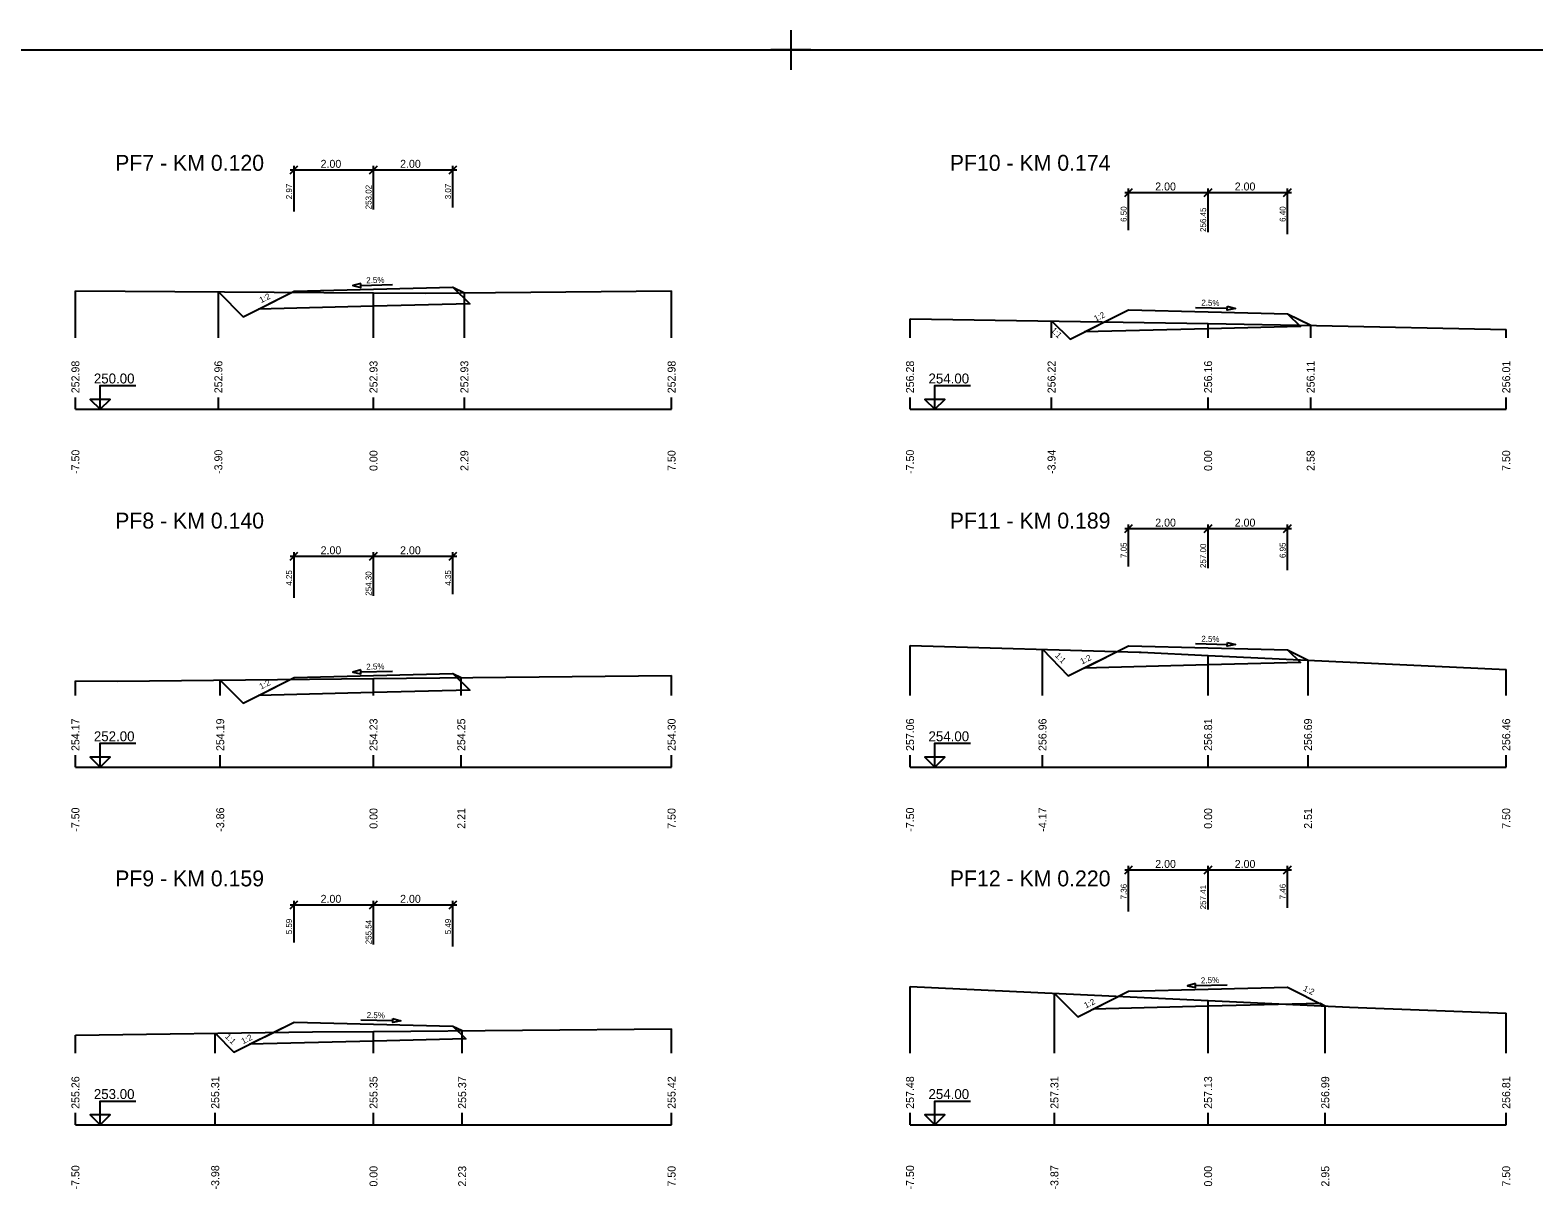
# Model space of a CAD drawing. Extents: x -5 to 1895, y -2 to 602.
# Drawn here: x 438.6 to 817, y 308.1 to 602.4 of the extents above; entities that cross this region are included whole.
import ezdxf

# ---------------------------------------------------------------- set-up
doc = ezdxf.new("R2010")
doc.units = 0
for name, color, linetype in [('KOTA', 7, 'Continuous'), ('KOTA_DELKY', 7, 'Continuous'), ('KOTA_DELKY_CONT', 7, 'Continuous'), ('NS_TELESO_VOZOVKY', 7, 'Continuous'), ('NS_V_PF', 7, 'Continuous'), ('REZY_PF_PUVODNI', 7, 'Continuous'), ('SESTAVY_REZU_PF', 7, 'Continuous'), ('SKLON', 7, 'Continuous'), ('SVK', 7, 'Continuous')]:
    doc.layers.add(name, color=color, linetype=linetype)

msp = doc.modelspace()

# ---------------------------------------------------------------- linework, layer by layer
for p, q in [((630, 602.39), (630, 592.39)), ((630, 602.39), (630, 592.39)), ((630, 602.39), (630, 592.39)), ((630, 602.39), (630, 592.39)), ((630, 602.39), (630, 592.39)), ((630, 602.39), (630, 592.39)), ((630, 602.39), (630, 592.39)), ((630, 602.39), (630, 592.39)), ((630, 602.39), (630, 592.39)), ((630, 602.39), (630, 592.39)), ((630, 602.39), (630, 592.39)), ((630, 602.39), (630, 592.39)), ((630, 602.39), (630, 592.39)), ((630, 602.39), (630, 592.39)), ((630, 602.39), (630, 592.39)), ((630, 602.39), (630, 592.39)), ((630, 602.39), (630, 592.39)), ((630, 602.39), (630, 592.39)), ((635, 597.39), (625, 597.39)), ((635, 597.39), (625, 597.39)), ((635, 597.39), (625, 597.39)), ((635, 597.39), (625, 597.39)), ((635, 597.39), (625, 597.39)), ((635, 597.39), (625, 597.39)), ((635, 597.39), (625, 597.39)), ((635, 597.39), (625, 597.39)), ((635, 597.39), (625, 597.39)), ((635, 597.39), (625, 597.39)), ((635, 597.39), (625, 597.39)), ((635, 597.39), (625, 597.39)), ((635, 597.39), (625, 597.39)), ((635, 597.39), (625, 597.39)), ((635, 597.39), (625, 597.39)), ((635, 597.39), (625, 597.39)), ((635, 597.39), (625, 597.39)), ((635, 597.39), (625, 597.39))]:
    msp.add_line(p, q)
msp.add_lwpolyline([(0, 597.39), (1890, 597.39), (1890, 3.39), (0, 3.39)], close=True)
at = {"layer": 'KOTA'}
for points in [[(456.22, 509.5), (453.72, 509.5), (456.22, 507), (456.22, 513), (465.22, 513)], [(666.22, 509.5), (663.72, 509.5), (666.22, 507), (666.22, 513), (675.22, 513)], [(456.22, 507), (458.72, 509.5), (456.22, 509.5)], [(666.22, 507), (668.72, 509.5), (666.22, 509.5)], [(456.22, 419.5), (453.72, 419.5), (456.22, 417), (456.22, 423), (465.22, 423)], [(666.22, 419.5), (663.72, 419.5), (666.22, 417), (666.22, 423), (675.22, 423)], [(456.22, 417), (458.72, 419.5), (456.22, 419.5)], [(666.22, 417), (668.72, 419.5), (666.22, 419.5)], [(456.22, 329.5), (453.72, 329.5), (456.22, 327), (456.22, 333), (465.22, 333)], [(666.22, 329.5), (663.72, 329.5), (666.22, 327), (666.22, 333), (675.22, 333)], [(456.22, 327), (458.72, 329.5), (456.22, 329.5)], [(666.22, 327), (668.72, 329.5), (666.22, 329.5)]]:
    msp.add_lwpolyline(points, dxfattribs=at)
at = {"layer": 'KOTA_DELKY'}
for points in [[(504, 566.25), (506, 568.25)], [(505, 556.75), (505, 568.25)], [(524, 566.25), (526, 568.25)], [(524, 566.25), (526, 568.25)], [(525, 557.25), (525, 568.25)], [(525, 557.25), (525, 568.25)], [(544, 566.25), (546, 568.25)], [(545, 557.75), (545, 568.25)], [(504, 567.25), (526, 567.25)], [(524, 567.25), (546, 567.25)], [(714, 560.55), (716, 562.55)], [(714, 561.55), (736, 561.55)], [(715, 552.05), (715, 562.55)], [(734, 560.55), (736, 562.55)], [(734, 560.55), (736, 562.55)], [(734, 561.55), (756, 561.55)], [(735, 551.55), (735, 562.55)], [(735, 551.55), (735, 562.55)], [(754, 560.55), (756, 562.55)], [(755, 551.05), (755, 562.55)], [(714, 476), (716, 478)], [(714, 477), (736, 477)], [(715, 467.5), (715, 478)], [(734, 476), (736, 478)], [(734, 476), (736, 478)], [(734, 477), (756, 477)], [(735, 467), (735, 478)], [(735, 467), (735, 478)], [(754, 476), (756, 478)], [(755, 466.5), (755, 478)], [(504, 469.04), (506, 471.04)], [(504, 470.04), (526, 470.04)], [(505, 459.54), (505, 471.04)], [(524, 469.04), (526, 471.04)], [(524, 469.04), (526, 471.04)], [(524, 470.04), (546, 470.04)], [(525, 460.04), (525, 471.04)], [(525, 460.04), (525, 471.04)], [(544, 469.04), (546, 471.04)], [(545, 460.54), (545, 471.04)], [(714, 390.14), (716, 392.14)], [(714, 391.14), (736, 391.14)], [(715, 380.64), (715, 392.14)], [(734, 390.14), (736, 392.14)], [(734, 390.14), (736, 392.14)], [(734, 391.14), (756, 391.14)], [(735, 381.14), (735, 392.14)], [(735, 381.14), (735, 392.14)], [(754, 390.14), (756, 392.14)], [(755, 381.64), (755, 392.14)], [(504, 381.36), (506, 383.36)], [(504, 382.36), (526, 382.36)], [(505, 372.86), (505, 383.36)], [(524, 381.36), (526, 383.36)], [(524, 381.36), (526, 383.36)], [(524, 382.36), (546, 382.36)], [(525, 372.36), (525, 383.36)], [(525, 372.36), (525, 383.36)], [(544, 381.36), (546, 383.36)], [(545, 371.86), (545, 383.36)]]:
    msp.add_lwpolyline(points, dxfattribs=at)
at = {"layer": 'NS_TELESO_VOZOVKY'}
for points in [[(525, 537.25), (545, 537.75), (545, 537.75), (549.2, 533.55), (525, 532.95), (496.05, 532.22), (505, 536.75), (505, 536.75), (525, 537.25)], [(735, 531.55), (755, 531.05), (755, 531.05), (758.22, 527.83), (735, 527.25), (703.9, 526.47), (715, 532.05), (715, 532.05), (735, 531.55)], [(735, 447), (755, 446.5), (755, 446.5), (758.22, 443.28), (735, 442.7), (703.77, 441.92), (715, 447.5), (715, 447.5), (735, 447)], [(525, 440.04), (545, 440.54), (545, 440.54), (549.2, 436.35), (525, 435.74), (496.05, 435.02), (505, 439.54), (505, 439.54), (525, 440.04)], [(735, 361.14), (755, 361.64), (755, 361.64), (764.47, 356.9), (763.19, 357.55), (735, 356.84), (706.05, 356.12), (715, 360.64), (715, 360.64), (735, 361.14)], [(525, 352.36), (545, 351.86), (545, 351.86), (548.22, 348.64), (525, 348.06), (493.83, 347.28), (505, 352.86), (505, 352.86), (525, 352.36)]]:
    msp.add_lwpolyline(points, dxfattribs=at)
at = {"layer": 'NS_V_PF'}
for points in [[(485.97, 536.56), (492.19, 530.27), (505, 536.75), (505, 536.75), (525, 537.25), (545, 537.75), (545, 537.75), (547.87, 536.31)], [(695.6, 529.22), (700.25, 524.64), (715, 532.05), (715, 532.05), (735, 531.55), (755, 531.05), (755, 531.05), (760.8, 528.15)], [(693.33, 446.64), (699.81, 439.95), (715, 447.5), (715, 447.5), (735, 447), (755, 446.5), (755, 446.5), (760.14, 443.93)], [(486.43, 438.89), (492.19, 433.07), (505, 439.54), (505, 439.54), (525, 440.04), (545, 440.54), (545, 440.54), (547.09, 439.5)], [(696.33, 360.08), (702.19, 354.16), (715, 360.64), (715, 360.64), (735, 361.14), (755, 361.64), (755, 361.64), (764.47, 356.9)], [(485.17, 350.05), (489.86, 345.29), (505, 352.86), (505, 352.86), (525, 352.36), (545, 351.86), (545, 351.86), (547.31, 350.71)]]:
    msp.add_lwpolyline(points, dxfattribs=at)
at = {"layer": 'REZY_PF_PUVODNI'}
for points in [[(450, 536.8), (525, 536.3), (538.01, 536.21), (600, 536.84)], [(660, 529.8), (735, 528.57), (762.28, 528.12), (810, 527.09)], [(660, 447.62), (717.65, 445.92), (718.15, 445.9), (735, 445.11), (810, 441.59)], [(450, 438.7), (460.6, 438.63), (525, 439.28), (600, 440.03)], [(660, 361.78), (735, 358.28), (770.58, 356.62), (810, 355.08)], [(450, 349.59), (509.65, 350.38), (525, 350.51), (600, 351.17)]]:
    msp.add_lwpolyline(points, dxfattribs=at)
at = {"layer": 'SESTAVY_REZU_PF'}
for points in [[(450, 507), (600, 507)], [(660, 507), (810, 507)], [(450, 417), (600, 417)], [(660, 417), (810, 417)], [(450, 327), (600, 327)], [(660, 327), (810, 327)]]:
    msp.add_lwpolyline(points, dxfattribs=at)
at = {"layer": 'SKLON'}
for points in [[(521.79, 538.67), (519.8, 538.12), (521.81, 537.67), (521.79, 538.67)], [(521.8, 538.17), (529.8, 538.37)], [(731.85, 532.63), (739.85, 532.43)], [(739.86, 532.93), (741.85, 532.38), (739.83, 531.93), (739.86, 532.93)], [(731.85, 448.08), (739.85, 447.88)], [(739.86, 448.38), (741.85, 447.83), (739.83, 447.38), (739.86, 448.38)], [(521.79, 441.47), (519.8, 440.92), (521.81, 440.47), (521.79, 441.47)], [(521.8, 440.97), (529.8, 441.17)], [(731.79, 362.56), (729.8, 362.01), (731.81, 361.56), (731.79, 362.56)], [(731.8, 362.06), (739.8, 362.26)], [(521.85, 353.44), (529.85, 353.24)], [(529.86, 353.74), (531.85, 353.19), (529.83, 352.74), (529.86, 353.74)]]:
    msp.add_lwpolyline(points, dxfattribs=at)
at = {"layer": 'SVK'}
for points in [[(450, 525), (450, 536.8)], [(485.97, 525), (485.97, 536.56)], [(525, 525), (525, 536.3)], [(547.87, 525), (547.87, 536.31)], [(600, 525), (600, 536.84)], [(660, 525), (660, 529.8)], [(695.6, 525), (695.6, 529.22)], [(735, 525), (735, 528.57)], [(760.8, 525), (760.8, 528.15)], [(810, 525), (810, 527.09)], [(450, 507), (450, 510)], [(485.97, 507), (485.97, 510)], [(525, 507), (525, 510)], [(547.87, 507), (547.87, 510)], [(600, 507), (600, 510)], [(660, 507), (660, 510)], [(695.6, 507), (695.6, 510)], [(735, 507), (735, 510)], [(760.8, 507), (760.8, 510)], [(810, 507), (810, 510)], [(660, 435), (660, 447.62)], [(693.33, 435), (693.33, 446.64)], [(735, 435), (735, 445.11)], [(760.14, 435), (760.14, 443.93)], [(525, 435), (525, 439.28)], [(547.09, 435), (547.09, 439.5)], [(600, 435), (600, 440.03)], [(810, 435), (810, 441.59)], [(450, 435), (450, 438.7)], [(486.43, 435), (486.43, 438.89)], [(450, 417), (450, 420)], [(486.43, 417), (486.43, 420)], [(525, 417), (525, 420)], [(547.09, 417), (547.09, 420)], [(600, 417), (600, 420)], [(660, 417), (660, 420)], [(693.33, 417), (693.33, 420)], [(735, 417), (735, 420)], [(760.14, 417), (760.14, 420)], [(810, 417), (810, 420)], [(660, 345), (660, 361.78)], [(696.33, 345), (696.33, 360.08)], [(735, 345), (735, 358.28)], [(764.47, 345), (764.47, 356.9)], [(810, 345), (810, 355.08)], [(450, 345), (450, 349.59)], [(485.17, 345), (485.17, 350.05)], [(525, 345), (525, 350.51)], [(547.31, 345), (547.31, 350.71)], [(600, 345), (600, 351.17)], [(450, 327), (450, 330)], [(485.17, 327), (485.17, 330)], [(525, 327), (525, 330)], [(547.31, 327), (547.31, 330)], [(600, 327), (600, 330)], [(660, 327), (660, 330)], [(696.33, 327), (696.33, 330)], [(735, 327), (735, 330)], [(764.47, 327), (764.47, 330)], [(810, 327), (810, 330)]]:
    msp.add_lwpolyline(points, dxfattribs=at)

# ---------------------------------------------------------------- texts
at = {"layer": 'KOTA'}
for s, p in [('250.00', (454.64, 513.5)), ('254.00', (664.64, 513.5)), ('252.00', (454.64, 423.5)), ('254.00', (664.64, 423.5)), ('253.00', (454.64, 333.5)), ('254.00', (664.64, 333.5))]:
    msp.add_text(s, height=2.5, dxfattribs=at).set_placement(p)
at = {"layer": 'KOTA_DELKY'}
for p in [(511.69, 567.75), (531.69, 567.75), (721.69, 562.05), (741.69, 562.05), (721.69, 477.5), (741.69, 477.5), (511.69, 470.54), (531.69, 470.54), (721.69, 391.64), (741.69, 391.64), (511.69, 382.86), (531.69, 382.86)]:
    msp.add_text('2.00', height=2, dxfattribs=at).set_placement(p)
at = {"layer": 'KOTA_DELKY_CONT'}
for s, p in [('2.97', (504.5, 559.84)), ('253.02', (524.5, 557.32)), ('3.07', (544.5, 559.84)), ('6.50', (714.5, 554.14)), ('256.45', (734.5, 551.62)), ('6.40', (754.5, 554.14)), ('7.05', (714.5, 469.59)), ('257.00', (734.5, 467.08)), ('6.95', (754.5, 469.59)), ('4.25', (504.5, 462.63)), ('254.30', (524.5, 460.12)), ('4.35', (544.5, 462.63)), ('7.36', (714.5, 383.73)), ('257.41', (734.5, 381.22)), ('7.46', (754.5, 383.73)), ('5.59', (504.5, 374.95)), ('255.54', (524.5, 372.44)), ('5.49', (544.5, 374.95))]:
    msp.add_text(s, height=1.5, rotation=90, dxfattribs=at).set_placement(p)
at = {"layer": 'SESTAVY_REZU_PF'}
for s, p in [('PF7 - KM 0.120', (460, 567)), ('PF10 - KM 0.174', (670, 567)), ('PF8 - KM 0.140', (460, 477)), ('PF11 - KM 0.189', (670, 477)), ('PF9 - KM 0.159', (460, 387)), ('PF12 - KM 0.220', (670, 387))]:
    msp.add_text(s, height=4, dxfattribs=at).set_placement(p)
at = {"layer": 'SKLON'}
for s, rotation, p in [('2.5%', 1.4321, (523.2, 538.7)), ('1:2', 26.8233, (496.74, 533.69)), ('2.5%', 358.5679, (733.27, 533.09)), ('1:2', 26.6688, (706.74, 529.02)), ('1:1', 315.4346, (695.32, 526.73)), ('2.5%', 358.5679, (733.27, 448.54)), ('2.5%', 1.4321, (523.2, 441.5)), ('1:1', 314.1179, (696.35, 444.95)), ('1:2', 26.4309, (703.28, 442.79)), ('1:2', 26.8233, (496.74, 436.49)), ('2.5%', 1.4321, (733.2, 362.6)), ('1:2', 333.4349, (758.77, 360.87)), ('1:2', 26.8233, (704.24, 356.26)), ('2.5%', 358.5679, (523.27, 353.9)), ('1:1', 314.5713, (487.52, 349.1)), ('1:2', 26.5484, (492.19, 347.28))]:
    msp.add_text(s, height=1.5, rotation=rotation, dxfattribs=at).set_placement(p)
at = {"layer": 'SVK'}
for s, p in [(' 252.98', (451, 510.3)), (' 252.96', (486.97, 510.3)), (' 252.93', (526, 510.3)), (' 252.93', (548.87, 510.3)), (' 252.98', (601, 510.3)), (' 256.28', (661, 510.3)), (' 256.22', (696.6, 510.3)), (' 256.16', (736, 510.3)), (' 256.11', (761.8, 510.3)), (' 256.01', (811, 510.3)), (' -7.50', (451, 490)), (' -3.90', (486.97, 490)), ('  0.00', (526, 490)), ('  2.29', (548.87, 490)), ('  7.50', (601, 490)), (' -7.50', (661, 490)), (' -3.94', (696.6, 490)), ('  0.00', (736, 490)), ('  2.58', (761.8, 490)), ('  7.50', (811, 490)), (' 254.17', (451, 420.3)), (' 254.19', (487.43, 420.3)), (' 254.23', (526, 420.3)), (' 254.25', (548.09, 420.3)), (' 254.30', (601, 420.3)), (' 257.06', (661, 420.3)), (' 256.96', (694.33, 420.3)), (' 256.81', (736, 420.3)), (' 256.69', (761.14, 420.3)), (' 256.46', (811, 420.3)), (' -7.50', (451, 400)), (' -3.86', (487.43, 400)), ('  0.00', (526, 400)), ('  2.21', (548.09, 400)), ('  7.50', (601, 400)), (' -7.50', (661, 400)), (' -4.17', (694.33, 400)), ('  0.00', (736, 400)), ('  2.51', (761.14, 400)), ('  7.50', (811, 400)), (' 255.26', (451, 330.3)), (' 255.31', (486.17, 330.3)), (' 255.35', (526, 330.3)), (' 255.37', (548.31, 330.3)), (' 255.42', (601, 330.3)), (' 257.48', (661, 330.3)), (' 257.31', (697.33, 330.3)), (' 257.13', (736, 330.3)), (' 256.99', (765.47, 330.3)), (' 256.81', (811, 330.3)), (' -7.50', (451, 310)), (' -3.98', (486.17, 310)), ('  0.00', (526, 310)), ('  2.23', (548.31, 310)), ('  7.50', (601, 310)), (' -7.50', (661, 310)), (' -3.87', (697.33, 310)), ('  0.00', (736, 310)), ('  2.95', (765.47, 310)), ('  7.50', (811, 310))]:
    msp.add_text(s, height=2, rotation=90, dxfattribs=at).set_placement(p)

doc.saveas('drawing.dxf')
